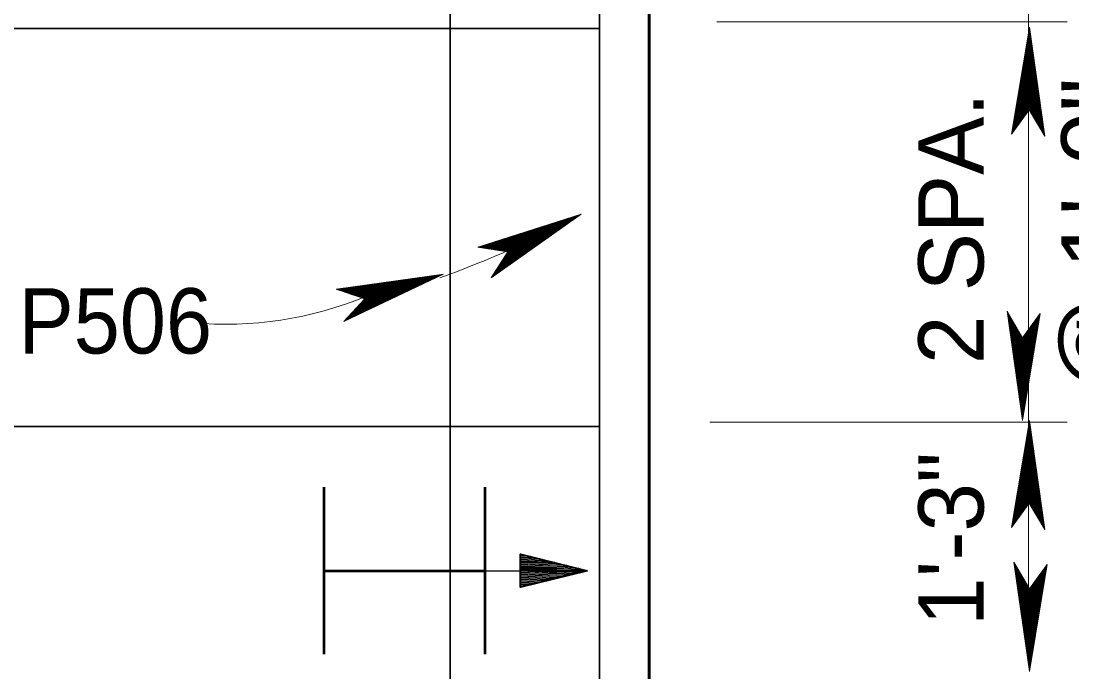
# Model space of a CAD drawing. Extents: x 144 to 252, y 360 to 425.
# Drawn here: x 177.62 to 182.91, y 412.64 to 415.91 of the extents above; entities that cross this region are included whole.
import ezdxf
from ezdxf.enums import TextEntityAlignment as Align

# ---------------------------------------------------------------- set-up
doc = ezdxf.new("R2010")
doc.units = 0
doc.header["$LTSCALE"] = 0.13
for name, color, linetype, lineweight in [('1', 7, 'Continuous', 40), ('10', 7, 'Continuous', 35), ('16', 7, 'Continuous', 13), ('3', 7, 'Continuous', 13), ('9', 7, 'Continuous', 25)]:
    doc.layers.add(name, color=color, linetype=linetype, lineweight=lineweight)

msp = doc.modelspace()

# ---------------------------------------------------------------- linework, layer by layer
at = {"layer": '1', "lineweight": 35}
for p, q in [((179.7812, 412.1206), (179.7812, 417.6206)), ((180.5312, 412.1206), (180.5312, 417.6206)), ((168.8907, 415.8706), (180.5312, 415.8706)), ((168.9595, 413.8706), (180.5312, 413.8706)), ((168.9602, 413.8706), (180.5312, 413.8706))]:
    msp.add_line(p, q, dxfattribs=at)
at = {"layer": '1', "lineweight": 13}
for p, q in [((182.688, 412.7358), (182.688, 417.1045)), ((182.8819, 415.904), (181.1214, 415.904)), ((182.8819, 413.8912), (181.0861, 413.8912))]:
    msp.add_line(p, q, dxfattribs=at)
at = {"layer": '1', "lineweight": 53}
for p, q in [((179.1473, 412.7252), (179.1473, 413.5648)), ((179.9557, 412.7252), (179.9557, 413.5648)), ((179.1473, 413.145), (179.9557, 413.145))]:
    msp.add_line(p, q, dxfattribs=at)
at = {"layer": '1', "lineweight": 25}
msp.add_line((179.9557, 413.145), (180.4557, 413.145), dxfattribs=at)
at = {"layer": '1', "lineweight": 60}
msp.add_lwpolyline([(156.7812, 417.8706), (180.7812, 417.8706), (180.7812, 411.8706), (156.7812, 411.8706)], close=True, dxfattribs=at)
at = {"layer": '10'}
for p, q in [((180.1335, 413.1932), (180.3061, 413.1859)), ((180.3174, 413.1603), (180.1335, 413.168)), ((180.3173, 413.154), (180.1335, 413.1617)), ((180.1335, 413.1554), (180.3172, 413.1477)), ((180.317, 413.1415), (180.1335, 413.1492)), ((180.1335, 413.1454), (180.4688, 413.1454))]:
    msp.add_line(p, q, dxfattribs=at)
for points in [[(180.1335, 413.0619), (180.1335, 413.2288), (180.4688, 413.1455)], [(180.1335, 413.0619), (180.4688, 413.1455), (180.1335, 413.0619)]]:
    msp.add_lwpolyline(points, dxfattribs=at)
msp.add_lwpolyline([(180.4688, 413.1455), (180.1335, 413.0619), (180.1335, 413.2288), (180.1335, 413.0619)], close=True, dxfattribs=at)
at = {"layer": '16'}
msp.add_arc((178.1617, 419.0493), 4.7005, 289.4807, 298.9787, dxfattribs=at)
at = {"layer": '3'}
for p, q in [((182.6919, 415.8773), (182.6027, 415.3396)), ((182.6912, 415.8628), (182.605, 415.3428)), ((182.6912, 415.852), (182.6073, 415.3461)), ((182.6912, 415.8376), (182.6105, 415.3503)), ((182.7662, 415.3345), (182.6912, 415.8628)), ((182.7642, 415.338), (182.6912, 415.852)), ((182.7615, 415.3426), (182.6912, 415.8376)), ((182.6919, 415.4618), (182.6919, 415.8773)), ((182.7697, 415.3285), (182.6919, 415.8773)), ((182.6912, 415.8248), (182.6132, 415.3541)), ((182.6912, 415.8135), (182.6156, 415.3574)), ((182.6912, 415.7991), (182.6188, 415.3617)), ((182.6912, 415.7863), (182.6215, 415.3654)), ((182.7591, 415.3467), (182.6912, 415.8248)), ((182.7591, 415.3467), (182.6912, 415.8248)), ((182.7569, 415.3503), (182.6912, 415.8135)), ((182.7542, 415.3549), (182.6912, 415.7991)), ((182.7518, 415.359), (182.6912, 415.7863)), ((182.6912, 415.7726), (182.6244, 415.3695)), ((182.6912, 415.7587), (182.6274, 415.3736)), ((182.6912, 415.7455), (182.6302, 415.3775)), ((182.6912, 415.7316), (182.6333, 415.3816)), ((182.7493, 415.3634), (182.6912, 415.7726)), ((182.7467, 415.3678), (182.6912, 415.7587)), ((182.7442, 415.3721), (182.6912, 415.7455)), ((182.7416, 415.3766), (182.6912, 415.7316)), ((182.6912, 415.719), (182.6359, 415.3853)), ((182.6912, 415.7076), (182.6384, 415.3887)), ((182.6912, 415.6919), (182.6418, 415.3933)), ((182.6912, 415.6781), (182.6447, 415.3974)), ((182.7393, 415.3806), (182.6912, 415.719)), ((182.7371, 415.3843), (182.6912, 415.7076)), ((182.7343, 415.3893), (182.6912, 415.6919)), ((182.7316, 415.3938), (182.6912, 415.6781)), ((182.6907, 415.6601), (182.6478, 415.4017)), ((182.6907, 415.6462), (182.6508, 415.4058)), ((182.6907, 415.633), (182.6537, 415.4097)), ((182.6912, 415.6239), (182.6564, 415.4134)), ((182.7274, 415.4009), (182.6907, 415.6601)), ((182.7248, 415.4053), (182.6907, 415.6462)), ((182.7223, 415.4096), (182.6907, 415.633)), ((182.7215, 415.4111), (182.6912, 415.6239)), ((182.7293, 415.3977), (182.6923, 415.6585)), ((182.6912, 415.6119), (182.659, 415.417)), ((182.6912, 415.5981), (182.662, 415.4211)), ((182.6912, 415.5824), (182.6652, 415.4257)), ((182.6912, 415.5698), (182.668, 415.4294)), ((182.7192, 415.415), (182.6912, 415.6119)), ((182.7166, 415.4194), (182.6912, 415.5981)), ((182.7138, 415.4244), (182.6912, 415.5824)), ((182.7113, 415.4285), (182.6912, 415.5698)), ((182.6912, 415.5566), (182.6708, 415.4333)), ((182.6912, 415.5446), (182.6735, 415.4369)), ((182.6912, 415.5301), (182.6765, 415.4412)), ((182.7088, 415.4327), (182.6912, 415.5566)), ((182.7066, 415.4366), (182.6912, 415.5446)), ((182.7039, 415.4412), (182.6912, 415.5301)), ((182.6912, 415.5163), (182.6795, 415.4453)), ((182.6912, 415.5036), (182.6822, 415.449)), ((182.6912, 415.4903), (182.6851, 415.4529)), ((182.6912, 415.4789), (182.6875, 415.4563)), ((182.6912, 415.4688), (182.6898, 415.4593)), ((182.7013, 415.4457), (182.6912, 415.5163)), ((182.699, 415.4497), (182.6912, 415.5036)), ((182.6943, 415.4577), (182.6912, 415.4789)), ((182.6959, 415.455), (182.6923, 415.4801)), ((182.6027, 415.3396), (182.6917, 415.4621)), ((182.6917, 415.4621), (182.7697, 415.3285)), ((180.439, 414.9373), (179.9201, 414.7707)), ((179.9866, 414.6172), (180.439, 414.9373)), ((180.0696, 414.7473), (180.439, 414.9373)), ((180.4258, 414.9313), (179.924, 414.7702)), ((180.4162, 414.9264), (179.928, 414.7696)), ((180.4034, 414.9197), (179.9332, 414.7688)), ((180.3921, 414.9139), (179.9377, 414.7681)), ((180.382, 414.9087), (179.9418, 414.7674)), ((180.3692, 414.9022), (179.9471, 414.7666)), ((180.3578, 414.8963), (179.9517, 414.7658)), ((180.3456, 414.8901), (179.9566, 414.7651)), ((180.3333, 414.8837), (179.9616, 414.7643)), ((179.9903, 414.6231), (180.4258, 414.9313)), ((179.9925, 414.6264), (180.4162, 414.9264)), ((179.9953, 414.6309), (180.4034, 414.9197)), ((179.9979, 414.6349), (180.3921, 414.9139)), ((179.9979, 414.6349), (180.3921, 414.9139)), ((180.0002, 414.6385), (180.382, 414.9087)), ((180.003, 414.643), (180.3692, 414.9022)), ((180.0056, 414.647), (180.3578, 414.8963)), ((180.0083, 414.6513), (180.3456, 414.8901)), ((180.0111, 414.6556), (180.3333, 414.8837)), ((180.3215, 414.8777), (179.9664, 414.7636)), ((180.3092, 414.8713), (179.9714, 414.7627)), ((180.298, 414.8655), (179.9759, 414.7622)), ((180.2878, 414.8603), (179.9802, 414.7615)), ((180.2739, 414.8532), (179.9857, 414.7606)), ((180.2616, 414.8468), (179.9907, 414.7598)), ((180.2453, 414.839), (179.9959, 414.759)), ((180.233, 414.8327), (180.001, 414.7582)), ((180.0137, 414.6597), (180.3215, 414.8777)), ((180.0165, 414.6642), (180.3092, 414.8713)), ((180.019, 414.668), (180.298, 414.8655)), ((180.0213, 414.6717), (180.2878, 414.8603)), ((180.0245, 414.6765), (180.2739, 414.8532)), ((180.0272, 414.6809), (180.2616, 414.8468)), ((180.0298, 414.6848), (180.2447, 414.8369)), ((180.0317, 414.6879), (180.2453, 414.839)), ((180.0344, 414.6922), (180.233, 414.8327)), ((180.2212, 414.8267), (180.0057, 414.7575)), ((180.2134, 414.8221), (180.0103, 414.7568)), ((180.2027, 414.8166), (180.0147, 414.7561)), ((180.1904, 414.8102), (180.0197, 414.7552)), ((180.1765, 414.8031), (180.0253, 414.7545)), ((180.1653, 414.7973), (180.0298, 414.7537)), ((180.1535, 414.7912), (180.0346, 414.753)), ((180.037, 414.6963), (180.2212, 414.8267)), ((180.038, 414.6978), (180.2134, 414.8221)), ((180.1428, 414.7858), (180.039, 414.7523)), ((180.0404, 414.7016), (180.2027, 414.8166)), ((180.0432, 414.706), (180.1904, 414.8102)), ((180.13, 414.7792), (180.0442, 414.7516)), ((180.0463, 414.7107), (180.1765, 414.8031)), ((180.0488, 414.7148), (180.1653, 414.7973)), ((180.0515, 414.719), (180.1535, 414.7912)), ((180.0538, 414.7227), (180.1428, 414.7858)), ((180.0567, 414.7272), (180.13, 414.7792)), ((179.9201, 414.7707), (180.0697, 414.7476)), ((180.0697, 414.7476), (179.9866, 414.6172)), ((180.1177, 414.7728), (180.0493, 414.7508)), ((180.1064, 414.767), (180.0538, 414.7501)), ((180.0947, 414.7609), (180.0585, 414.7493)), ((180.0595, 414.7316), (180.1177, 414.7728)), ((180.0621, 414.7355), (180.1064, 414.767)), ((180.0845, 414.7557), (180.0627, 414.7487)), ((180.0653, 414.7407), (180.086, 414.7553)), ((180.0754, 414.7511), (180.0663, 414.7481)), ((180.067, 414.7432), (180.0845, 414.7557)), ((179.747, 414.6357), (179.2072, 414.5599)), ((179.7331, 414.632), (179.2111, 414.5587)), ((179.7227, 414.6287), (179.2148, 414.5573)), ((179.7089, 414.6244), (179.2198, 414.5556)), ((179.6967, 414.6206), (179.2242, 414.5542)), ((179.2467, 414.3972), (179.747, 414.6357)), ((179.2513, 414.4023), (179.7331, 414.632)), ((179.2541, 414.4053), (179.7227, 414.6287)), ((179.2577, 414.4092), (179.7089, 414.6244)), ((179.2608, 414.4127), (179.6967, 414.6206)), ((179.2608, 414.4127), (179.6967, 414.6206)), ((179.3507, 414.5113), (179.747, 414.6357)), ((179.686, 414.6173), (179.2282, 414.5529)), ((179.6722, 414.6129), (179.2332, 414.5512)), ((179.6601, 414.6091), (179.2376, 414.5497)), ((179.6469, 414.605), (179.2423, 414.5481)), ((179.6337, 414.6008), (179.2471, 414.5464)), ((179.6211, 414.5968), (179.2517, 414.5449)), ((179.6078, 414.5927), (179.2565, 414.5433)), ((179.5958, 414.5889), (179.2609, 414.5418)), ((179.2637, 414.4159), (179.686, 414.6173)), ((179.5849, 414.5855), (179.2649, 414.5405)), ((179.2672, 414.4198), (179.6722, 414.6129)), ((179.57, 414.5808), (179.2703, 414.5387)), ((179.2704, 414.4233), (179.6601, 414.6091)), ((179.2739, 414.4271), (179.6469, 414.605)), ((179.5567, 414.5767), (179.2751, 414.537)), ((179.2773, 414.4308), (179.6337, 414.6008)), ((179.5394, 414.5718), (179.28, 414.5353)), ((179.2807, 414.4345), (179.6211, 414.5968)), ((179.2842, 414.4384), (179.6078, 414.5927)), ((179.5262, 414.5676), (179.2849, 414.5337)), ((179.2873, 414.4418), (179.5958, 414.5889)), ((179.2902, 414.445), (179.5849, 414.5855)), ((179.2942, 414.4493), (179.57, 414.5808)), ((179.2976, 414.4531), (179.5567, 414.5767)), ((179.3007, 414.4564), (179.5384, 414.5697)), ((179.3032, 414.4592), (179.5394, 414.5718)), ((179.3066, 414.463), (179.5262, 414.5676)), ((179.2072, 414.5599), (179.3508, 414.5116)), ((179.5136, 414.5637), (179.2894, 414.5322)), ((179.5051, 414.5605), (179.2938, 414.5307)), ((179.4937, 414.5569), (179.298, 414.5293)), ((179.4804, 414.5528), (179.3028, 414.5277)), ((179.4655, 414.5481), (179.3082, 414.526)), ((179.3099, 414.4667), (179.5136, 414.5637)), ((179.3111, 414.4679), (179.5051, 414.5605)), ((179.4535, 414.5442), (179.3126, 414.5244)), ((179.3142, 414.4712), (179.4937, 414.5569)), ((179.4408, 414.5403), (179.3172, 414.5229)), ((179.3176, 414.4751), (179.4804, 414.5528)), ((179.4294, 414.5367), (179.3213, 414.5214)), ((179.3215, 414.4792), (179.4655, 414.5481)), ((179.3247, 414.4828), (179.4535, 414.5442)), ((179.4156, 414.5324), (179.3263, 414.5198)), ((179.3279, 414.4865), (179.4408, 414.5403)), ((179.3309, 414.4897), (179.4294, 414.5367)), ((179.4023, 414.5283), (179.3312, 414.5182)), ((179.3346, 414.4937), (179.4156, 414.5324)), ((179.3902, 414.5244), (179.3355, 414.5167)), ((179.338, 414.4975), (179.4023, 414.5283)), ((179.3777, 414.5205), (179.3401, 414.5152)), ((179.3413, 414.5009), (179.3902, 414.5244)), ((179.3667, 414.5171), (179.3441, 414.5139)), ((179.3453, 414.5054), (179.3682, 414.5164)), ((179.3474, 414.5077), (179.3667, 414.5171)), ((179.357, 414.514), (179.3476, 414.5127)), ((179.3508, 414.5116), (179.2467, 414.3972)), ((182.5801, 414.4493), (182.6578, 413.9006)), ((182.658, 414.3157), (182.5801, 414.4493)), ((182.5836, 414.4433), (182.6585, 413.915)), ((182.5856, 414.4398), (182.6585, 413.9258)), ((182.5882, 414.4352), (182.6585, 413.9402)), ((182.5907, 414.4312), (182.6585, 413.953)), ((182.5907, 414.4312), (182.6585, 413.953)), ((182.5928, 414.4275), (182.6585, 413.9643)), ((182.5955, 414.4229), (182.6585, 413.9787)), ((182.5979, 414.4188), (182.6585, 413.9915)), ((182.6004, 414.4144), (182.6585, 414.0052)), ((182.603, 414.41), (182.6585, 414.0191)), ((182.6578, 413.9006), (182.7471, 414.4382)), ((182.7471, 414.4382), (182.658, 414.3157)), ((182.6585, 413.915), (182.7447, 414.435)), ((182.6585, 413.9258), (182.7424, 414.4317)), ((182.6585, 413.9402), (182.7392, 414.4275)), ((182.6585, 413.953), (182.7366, 414.4237)), ((182.6585, 413.9643), (182.7342, 414.4204)), ((182.6585, 413.9787), (182.731, 414.4162)), ((182.6585, 413.9915), (182.7283, 414.4124)), ((182.6585, 414.0052), (182.7253, 414.4083)), ((182.6055, 414.4058), (182.6585, 414.0323)), ((182.6082, 414.4013), (182.6585, 414.0462)), ((182.6104, 414.3972), (182.6585, 414.0588)), ((182.6127, 414.3935), (182.6585, 414.0702)), ((182.6155, 414.3885), (182.6585, 414.0859)), ((182.6182, 414.3841), (182.6585, 414.0997)), ((182.6204, 414.3801), (182.6574, 414.1193)), ((182.6223, 414.3769), (182.659, 414.1178)), ((182.6249, 414.3725), (182.659, 414.1317)), ((182.6274, 414.3682), (182.659, 414.1448)), ((182.6282, 414.3667), (182.6585, 414.1539)), ((182.6305, 414.3628), (182.6585, 414.1659)), ((182.6332, 414.3584), (182.6585, 414.1798)), ((182.6585, 414.0191), (182.7223, 414.4042)), ((182.6585, 414.0323), (182.7195, 414.4003)), ((182.6585, 414.0462), (182.7165, 414.3963)), ((182.6585, 414.0588), (182.7138, 414.3925)), ((182.6585, 414.0702), (182.7113, 414.3891)), ((182.6585, 414.0859), (182.708, 414.3845)), ((182.6585, 414.0997), (182.705, 414.3804)), ((182.6585, 414.1539), (182.6933, 414.3644)), ((182.6585, 414.1659), (182.6907, 414.3608)), ((182.6585, 414.1798), (182.6877, 414.3567)), ((182.659, 414.1178), (182.7019, 414.3762)), ((182.659, 414.1317), (182.6989, 414.372)), ((182.659, 414.1448), (182.6961, 414.3682)), ((182.636, 414.3534), (182.6585, 414.1954)), ((182.6384, 414.3493), (182.6585, 414.208)), ((182.6409, 414.3451), (182.6585, 414.2212)), ((182.6432, 414.3413), (182.6585, 414.2332)), ((182.6458, 414.3366), (182.6585, 414.2477)), ((182.6484, 414.3322), (182.6585, 414.2616)), ((182.6507, 414.3281), (182.6585, 414.2742)), ((182.6538, 414.3228), (182.6574, 414.2978)), ((182.6554, 414.3202), (182.6585, 414.2989)), ((182.6578, 414.316), (182.6578, 413.9006)), ((182.6585, 414.1954), (182.6845, 414.3521)), ((182.6585, 414.208), (182.6817, 414.3484)), ((182.6585, 414.2212), (182.6789, 414.3445)), ((182.6585, 414.2332), (182.6762, 414.3409)), ((182.6585, 414.2477), (182.6732, 414.3367)), ((182.6585, 414.2616), (182.6702, 414.3325)), ((182.6585, 414.2742), (182.6675, 414.3288)), ((182.6585, 414.2875), (182.6647, 414.3249)), ((182.6585, 414.2989), (182.6623, 414.3215)), ((182.6585, 414.3091), (182.66, 414.3185)), ((182.6919, 413.9006), (182.6027, 413.3629)), ((182.6912, 413.8862), (182.605, 413.3662)), ((182.7662, 413.3578), (182.6912, 413.8862)), ((182.6919, 413.4852), (182.6919, 413.9006)), ((182.7697, 413.3518), (182.6919, 413.9006)), ((182.6912, 413.8753), (182.6073, 413.3694)), ((182.6912, 413.8609), (182.6105, 413.3737)), ((182.6912, 413.8482), (182.6132, 413.3774)), ((182.6912, 413.8368), (182.6156, 413.3807)), ((182.7642, 413.3613), (182.6912, 413.8753)), ((182.7615, 413.3659), (182.6912, 413.8609)), ((182.7591, 413.37), (182.6912, 413.8482)), ((182.7591, 413.37), (182.6912, 413.8482)), ((182.7569, 413.3737), (182.6912, 413.8368)), ((182.6912, 413.8224), (182.6188, 413.385)), ((182.6912, 413.8097), (182.6215, 413.3887)), ((182.6912, 413.7959), (182.6244, 413.3928)), ((182.6912, 413.7821), (182.6274, 413.3969)), ((182.7542, 413.3782), (182.6912, 413.8224)), ((182.7518, 413.3823), (182.6912, 413.8097)), ((182.7493, 413.3868), (182.6912, 413.7959)), ((182.7467, 413.3912), (182.6912, 413.7821)), ((182.6912, 413.7688), (182.6302, 413.4008)), ((182.6912, 413.7549), (182.6333, 413.4049)), ((182.6912, 413.7423), (182.6359, 413.4087)), ((182.6912, 413.7309), (182.6384, 413.4121)), ((182.7442, 413.3954), (182.6912, 413.7688)), ((182.7416, 413.3999), (182.6912, 413.7549)), ((182.7393, 413.4039), (182.6912, 413.7423)), ((182.7371, 413.4077), (182.6912, 413.7309)), ((182.6912, 413.7152), (182.6418, 413.4167)), ((182.6912, 413.7014), (182.6447, 413.4207)), ((182.6907, 413.6834), (182.6478, 413.425)), ((182.6907, 413.6695), (182.6508, 413.4292)), ((182.7274, 413.4242), (182.6907, 413.6834)), ((182.7248, 413.4287), (182.6907, 413.6695)), ((182.7343, 413.4127), (182.6912, 413.7152)), ((182.7316, 413.4171), (182.6912, 413.7014)), ((182.7293, 413.4211), (182.6923, 413.6818)), ((182.6907, 413.6563), (182.6537, 413.433)), ((182.6912, 413.6472), (182.6564, 413.4367)), ((182.6912, 413.6352), (182.659, 413.4403)), ((182.6912, 413.6214), (182.662, 413.4444)), ((182.7223, 413.4329), (182.6907, 413.6563)), ((182.7215, 413.4344), (182.6912, 413.6472)), ((182.7192, 413.4383), (182.6912, 413.6352)), ((182.7166, 413.4427), (182.6912, 413.6214)), ((182.6912, 413.6058), (182.6652, 413.4491)), ((182.6912, 413.5932), (182.668, 413.4527)), ((182.6912, 413.5799), (182.6708, 413.4567)), ((182.6912, 413.5679), (182.6735, 413.4602)), ((182.7138, 413.4477), (182.6912, 413.6058)), ((182.7113, 413.4518), (182.6912, 413.5932)), ((182.7088, 413.4561), (182.6912, 413.5799)), ((182.7066, 413.4599), (182.6912, 413.5679)), ((182.6912, 413.5534), (182.6765, 413.4645)), ((182.6912, 413.5396), (182.6795, 413.4687)), ((182.6912, 413.5269), (182.6822, 413.4723)), ((182.6912, 413.5137), (182.6851, 413.4762)), ((182.7039, 413.4646), (182.6912, 413.5534)), ((182.7013, 413.469), (182.6912, 413.5396)), ((182.699, 413.4731), (182.6912, 413.5269)), ((182.6027, 413.3629), (182.6917, 413.4854)), ((182.6912, 413.5023), (182.6875, 413.4797)), ((182.6912, 413.4921), (182.6898, 413.4827)), ((182.6943, 413.481), (182.6912, 413.5023)), ((182.6917, 413.4854), (182.7697, 413.3518)), ((182.6959, 413.4783), (182.6923, 413.5034)), ((182.6142, 413.1883), (182.6919, 412.6396)), ((182.6921, 413.0548), (182.6142, 413.1883)), ((182.6177, 413.1823), (182.6926, 412.654)), ((182.6197, 413.1788), (182.6926, 412.6648)), ((182.6223, 413.1742), (182.6926, 412.6792)), ((182.6248, 413.1702), (182.6926, 412.692)), ((182.6248, 413.1702), (182.6926, 412.692)), ((182.6269, 413.1665), (182.6926, 412.7033)), ((182.6296, 413.1619), (182.6926, 412.7177)), ((182.632, 413.1578), (182.6926, 412.7305)), ((182.6345, 413.1534), (182.6926, 412.7442)), ((182.6371, 413.149), (182.6926, 412.7581)), ((182.6396, 413.1447), (182.6926, 412.7713)), ((182.6422, 413.1402), (182.6926, 412.7852)), ((182.6919, 412.6396), (182.7812, 413.1772)), ((182.7812, 413.1772), (182.6921, 413.0548)), ((182.6926, 412.654), (182.7788, 413.174)), ((182.6926, 412.6648), (182.7765, 413.1707)), ((182.6926, 412.6792), (182.7733, 413.1665)), ((182.6926, 412.692), (182.7707, 413.1627)), ((182.6926, 412.7033), (182.7682, 413.1594)), ((182.6926, 412.7177), (182.7651, 413.1552)), ((182.6926, 412.7305), (182.7623, 413.1514)), ((182.6926, 412.7442), (182.7594, 413.1473)), ((182.6926, 412.7581), (182.7564, 413.1432)), ((182.6926, 412.7713), (182.7536, 413.1393)), ((182.6445, 413.1362), (182.6926, 412.7978)), ((182.6467, 413.1325), (182.6926, 412.8092)), ((182.6496, 413.1275), (182.6926, 412.8249)), ((182.6522, 413.1231), (182.6926, 412.8388)), ((182.6545, 413.1191), (182.6915, 412.8583)), ((182.6564, 413.1159), (182.6931, 412.8567)), ((182.659, 413.1115), (182.6931, 412.8707)), ((182.6615, 413.1072), (182.6931, 412.8838)), ((182.6623, 413.1058), (182.6926, 412.8929)), ((182.6646, 413.1018), (182.6926, 412.9049)), ((182.6672, 413.0974), (182.6926, 412.9187)), ((182.6701, 413.0924), (182.6926, 412.9344)), ((182.6725, 413.0883), (182.6926, 412.947)), ((182.6926, 412.7852), (182.7506, 413.1352)), ((182.6926, 412.7978), (182.7479, 413.1315)), ((182.6926, 412.8092), (182.7454, 413.1281)), ((182.6926, 412.8249), (182.7421, 413.1235)), ((182.6926, 412.8388), (182.7391, 413.1194)), ((182.6926, 412.8929), (182.7274, 413.1034)), ((182.6926, 412.9049), (182.7248, 413.0998)), ((182.6926, 412.9187), (182.7218, 413.0958)), ((182.6926, 412.9344), (182.7186, 413.0911)), ((182.6926, 412.947), (182.7158, 413.0874)), ((182.6931, 412.8567), (182.736, 413.1152)), ((182.6931, 412.8707), (182.733, 413.111)), ((182.6931, 412.8838), (182.7302, 413.1072)), ((182.675, 413.0841), (182.6926, 412.9602)), ((182.6772, 413.0802), (182.6926, 412.9722)), ((182.6799, 413.0756), (182.6926, 412.9867)), ((182.6825, 413.0712), (182.6926, 413.0006)), ((182.6848, 413.0671), (182.6926, 413.0132)), ((182.6879, 413.0618), (182.6915, 413.0367)), ((182.6895, 413.0592), (182.6926, 413.0379)), ((182.6919, 413.055), (182.6919, 412.6396)), ((182.6926, 412.9602), (182.713, 413.0835)), ((182.6926, 412.9722), (182.7103, 413.0799)), ((182.6926, 412.9867), (182.7073, 413.0757)), ((182.6926, 413.0006), (182.7043, 413.0715)), ((182.6926, 413.0132), (182.7016, 413.0678)), ((182.6926, 413.0265), (182.6987, 413.0639)), ((182.6926, 413.0379), (182.6963, 413.0605)), ((182.6926, 413.0481), (182.6941, 413.0575))]:
    msp.add_line(p, q, dxfattribs=at)
msp.add_arc((178.6525, 416.2228), 1.8391, 266.5055, 294.3177, dxfattribs=at)
at = {"layer": '9'}
for p, q in [((180.1542, 413.2237), (180.1335, 413.2246)), ((180.1845, 413.2162), (180.1335, 413.2183)), ((180.2149, 413.2086), (180.1335, 413.212)), ((180.2453, 413.2011), (180.1335, 413.2057)), ((180.2757, 413.1935), (180.1335, 413.1995)), ((180.3179, 413.1792), (180.1335, 413.1869)), ((180.3177, 413.1728), (180.1335, 413.1806)), ((180.3176, 413.1666), (180.1335, 413.1742)), ((180.3168, 413.1352), (180.1335, 413.1428)), ((180.4331, 413.1366), (180.317, 413.1415)), ((180.4547, 413.142), (180.3172, 413.1477)), ((180.4581, 413.1482), (180.3173, 413.154)), ((180.4277, 413.1557), (180.3174, 413.1603)), ((180.3972, 413.1633), (180.3176, 413.1666)), ((180.3669, 413.1708), (180.3177, 413.1728)), ((180.3365, 413.1784), (180.3179, 413.1792)), ((180.3167, 413.1289), (180.1335, 413.1366)), ((180.3165, 413.1226), (180.1335, 413.1303)), ((180.3163, 413.1163), (180.1335, 413.124)), ((180.3162, 413.1101), (180.1335, 413.1177)), ((180.3035, 413.1043), (180.1335, 413.1114)), ((180.2819, 413.0989), (180.1335, 413.1052)), ((180.2603, 413.0936), (180.1335, 413.0988)), ((180.2387, 413.0882), (180.1335, 413.0925)), ((180.3251, 413.1097), (180.3162, 413.1101)), ((180.3467, 413.1151), (180.3163, 413.1163)), ((180.3683, 413.1205), (180.3165, 413.1226)), ((180.3899, 413.1258), (180.3167, 413.1289)), ((180.4115, 413.1312), (180.3168, 413.1352)), ((180.2172, 413.0827), (180.1335, 413.0863)), ((180.1956, 413.0774), (180.1335, 413.08)), ((180.1739, 413.072), (180.1335, 413.0737)), ((180.1523, 413.0666), (180.1335, 413.0674))]:
    msp.add_line(p, q, dxfattribs=at)
at = {"layer": '9', "lineweight": 40}
msp.add_lwpolyline([(180.4688, 413.1455), (180.1335, 413.0619), (180.1335, 413.2288)], close=True, dxfattribs=at)

# ---------------------------------------------------------------- texts
at = {"layer": '16', "width": 1.1}
msp.add_text('@ 1\'-0"', height=0.3281, rotation=90, dxfattribs=at).set_placement((183.1803, 414.8309), align=Align.CENTER)
at = {"layer": '16'}
for s, p in [('2 SPA.', (182.4619, 414.8663)), ('1\'-3"', (182.4619, 413.3049))]:
    msp.add_text(s, height=0.3281, rotation=90, dxfattribs=at).set_placement(p, align=Align.CENTER)
at = {"layer": '16', "width": 0.95}
msp.add_text('P506', height=0.3281, dxfattribs=at).set_placement((178.0967, 414.2367), align=Align.CENTER)

doc.saveas('drawing.dxf')
